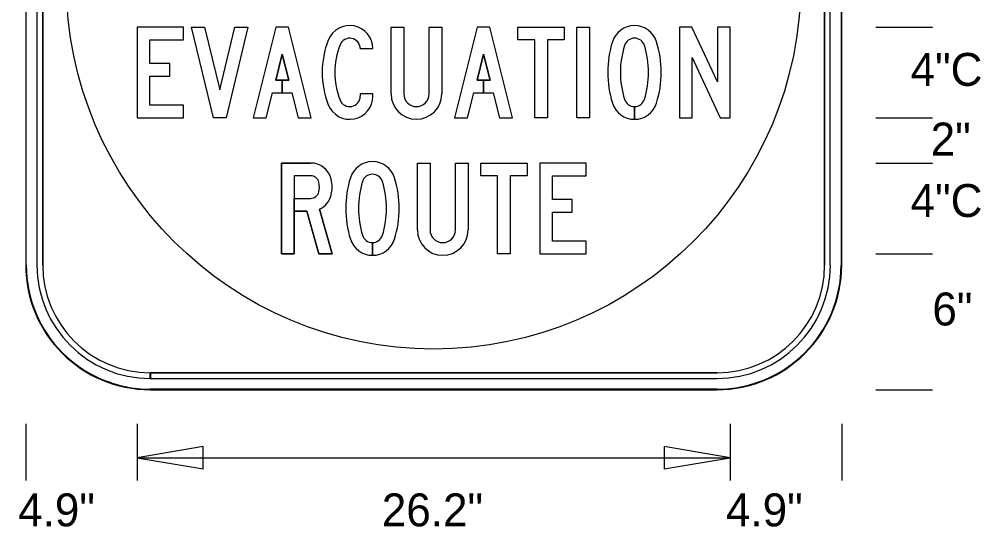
# Model space of a CAD drawing. Extents: x 0 to 770, y 0 to 495.
# Drawn here: x 644.3 to 746.6, y 366.6 to 420.6 of the extents above; entities that cross this region are included whole.
import ezdxf

# ---------------------------------------------------------------- set-up
doc = ezdxf.new("R2010")
doc.units = 0
for name, color, linetype in [('Dimension', 7, 'Continuous'), ('GSBWFill', 7, 'Continuous'), ('GSColorFill', 7, 'Continuous'), ('GSDims', 7, 'Continuous'), ('GSOutline', 7, 'Continuous'), ('IndexDetail_0', 7, 'Continuous'), ('TextStructures', 7, 'Continuous')]:
    doc.layers.add(name, color=color, linetype=linetype)

msp = doc.modelspace()

# ---------------------------------------------------------------- linework, layer by layer
at = {"layer": 'Dimension'}
for points in [[(656.84, 373.93), (663.86, 372.75), (663.86, 375.12)], [(719.93, 373.93), (712.91, 375.12), (712.91, 372.75)]]:
    msp.add_lwpolyline(points, close=True, dxfattribs=at)
at = {"layer": 'GSBWFill'}
for p, q in [((644.98, 454.72), (644.98, 394.43)), ((646.18, 454.72), (646.18, 394.43)), ((646.79, 394.43), (646.79, 454.72)), ((729.98, 454.72), (729.98, 394.43)), ((730.58, 394.43), (730.58, 454.72)), ((731.79, 394.43), (731.79, 454.72)), ((685.2, 419.75), (685.2, 412.64)), ((680.57, 417.46), (681.92, 417.46)), ((709.75, 411.29), (709.75, 409.94)), ((709.75, 409.94), (709.75, 411.29)), ((688, 405.28), (688, 398.17)), ((675.28, 401.52), (675.28, 401.52)), ((681.87, 396.82), (681.87, 395.47)), ((681.87, 395.47), (681.87, 396.82)), ((658.24, 382.37), (658.24, 382.98)), ((718.53, 382.98), (658.25, 382.98)), ((658.25, 382.98), (658.25, 382.37)), ((658.25, 382.37), (718.53, 382.37)), ((658.24, 381.17), (718.53, 381.17))]:
    msp.add_line(p, q, dxfattribs=at)
for points in [[(658.19, 411.46), (658.19, 414.54), (660.31, 414.54), (660.31, 415.89), (658.19, 415.89), (658.19, 418.4), (661.76, 418.4), (661.76, 419.75), (656.84, 419.75), (656.84, 410.11), (661.76, 410.11), (661.76, 411.46)], [(662.63, 419.75), (664.02, 419.75), (665.62, 413.08), (667.22, 419.75), (668.61, 419.75), (666.3, 410.11), (664.95, 410.11)], [(672.28, 414.11), (671.58, 414.11), (672.28, 416.88), (672.97, 414.11), (672.28, 414.11), (672.28, 412.76), (673.31, 412.76), (673.97, 410.11), (675.36, 410.11), (672.95, 419.75), (671.6, 419.75), (669.19, 410.11), (670.58, 410.11), (671.24, 412.76), (672.28, 412.76)], [(693.69, 414.11), (693, 414.11), (693.69, 416.88), (694.38, 414.11), (693.69, 414.11), (693.69, 412.76), (694.72, 412.76), (695.38, 410.11), (696.78, 410.11), (694.36, 419.75), (693.01, 419.75), (690.6, 410.11), (691.99, 410.11), (692.66, 412.76), (693.69, 412.76)], [(699.14, 418.4), (697.35, 418.4), (697.35, 419.75), (702.27, 419.75), (702.27, 418.4), (700.49, 418.4), (700.49, 410.11), (699.14, 410.11)], [(703.62, 419.75), (704.97, 419.75), (704.97, 410.11), (703.62, 410.11)], [(718.86, 410.11), (719.93, 410.11), (719.93, 419.75), (718.58, 419.75), (718.58, 413.92), (715.86, 419.75), (714.52, 419.75), (714.52, 410.11), (715.87, 410.11), (715.87, 416.52)], [(695.18, 403.93), (693.4, 403.93), (693.4, 405.28), (698.32, 405.28), (698.32, 403.93), (696.53, 403.93), (696.53, 395.64), (695.18, 395.64)], [(701.02, 396.99), (701.02, 400.07), (703.13, 400.07), (703.13, 401.42), (701.02, 401.42), (701.02, 403.93), (704.59, 403.93), (704.59, 405.28), (699.67, 405.28), (699.67, 395.64), (704.59, 395.64), (704.59, 396.99)]]:
    msp.add_lwpolyline(points, close=True, dxfattribs=at)
for points in [[(683.85, 412.64), (683.85, 419.75), (685.2, 419.75)], [(687.9, 412.64), (687.9, 419.75), (689.25, 419.75), (689.25, 412.64)], [(681.92, 412.4), (681.92, 412.66), (680.57, 412.66), (680.57, 412.4)], [(675.28, 403.93), (673.53, 403.93), (673.53, 395.64), (672.18, 395.64), (672.18, 405.28), (675.28, 405.28)], [(686.65, 398.17), (686.65, 405.28), (688, 405.28)], [(690.7, 398.17), (690.7, 405.28), (692.05, 405.28), (692.05, 398.17)], [(676.23, 400.38), (677.58, 395.64), (676.18, 395.64), (674.89, 400.17), (673.53, 400.17), (673.53, 401.52), (675.28, 401.52)]]:
    msp.add_lwpolyline(points, dxfattribs=at)
for centre, radius, start, end in [((709.75, 417.46), 2.46, 17.3283, 162.6717), ((709.75, 417.46), 1.11, 17.3283, 162.6717), ((717.86, 414.93), 10.96, 162.6717, 197.3283), ((717.86, 414.93), 9.61, 162.6717, 197.3283), ((701.63, 414.93), 9.61, 342.6717, 17.3283), ((701.63, 414.93), 10.96, 342.6717, 17.3283), ((686.55, 412.64), 2.7, 180, 0), ((686.55, 412.64), 1.35, 180, 0), ((709.75, 412.4), 2.46, 197.3283, 270), ((709.75, 412.4), 1.11, 197.3283, 270), ((709.75, 412.4), 1.11, 270.0249, 342.6717), ((709.75, 412.4), 2.46, 270.0112, 342.6717), ((675.28, 403.02), 2.27, 13.8865, 90), ((681.87, 402.99), 2.46, 17.3283, 162.6717), ((681.87, 402.99), 1.11, 17.3283, 162.6717), ((675.28, 403.02), 0.916, 13.8865, 90), ((674.11, 402.73), 2.12, 346.1135, 13.8865), ((674.11, 402.73), 3.47, 346.1135, 13.8865), ((689.99, 400.46), 10.96, 162.6717, 197.3283), ((689.99, 400.46), 9.61, 162.6717, 197.3283), ((673.76, 400.46), 9.61, 342.6717, 17.3283), ((673.76, 400.46), 10.96, 342.6717, 17.3283), ((675.28, 402.44), 0.916, 270, 346.1135), ((675.28, 402.44), 2.27, 294.8221, 346.1135), ((689.35, 398.17), 2.7, 180, 0), ((689.35, 398.17), 1.35, 180, 0), ((681.87, 397.93), 2.46, 197.3283, 270), ((681.87, 397.93), 1.11, 197.3283, 270), ((681.87, 397.93), 1.11, 270.0249, 342.6717), ((681.87, 397.93), 2.46, 270.0112, 342.6717), ((658.24, 394.43), 13.26, 180, 270), ((658.24, 394.43), 12.06, 180, 270), ((658.24, 394.43), 11.45, 180, 270), ((718.53, 394.43), 12.06, 270, 0), ((718.53, 394.43), 11.45, 270, 0), ((718.53, 394.43), 13.26, 270, 0)]:
    msp.add_arc(centre, radius, start, end, dxfattribs=at)
for centre, major_axis, start_param, end_param in [((679.46, 417.46), (0, 2.46), 4.712389, 7.477539), ((679.46, 417.46), (0, 1.11), 4.712389, 7.477539), ((685.87, 414.93), (0, 9.35), 1.194353, 1.947239), ((685.87, 414.93), (0, 8), 1.194353, 1.947239), ((679.46, 412.4), (0, 2.46), 1.947239, 4.712389), ((679.46, 412.4), (0, 1.11), 1.947239, 4.712389)]:
    msp.add_ellipse(centre, major_axis=major_axis, ratio=0.999991, start_param=start_param, end_param=end_param, dxfattribs=at)
at = {"layer": 'GSColorFill'}
for p, q in [((644.98, 454.72), (644.98, 394.43)), ((644.98, 454.72), (644.98, 394.43)), ((645.04, 394.43), (645.04, 454.72)), ((646.18, 454.72), (646.18, 394.43)), ((646.79, 394.43), (646.79, 454.72)), ((729.98, 454.72), (729.98, 394.43)), ((730.58, 394.43), (730.58, 454.72)), ((731.73, 454.72), (731.73, 394.43)), ((731.79, 394.43), (731.79, 454.72)), ((731.79, 394.43), (731.79, 454.72)), ((685.2, 419.75), (685.2, 412.64)), ((680.57, 417.46), (681.92, 417.46)), ((709.75, 411.29), (709.75, 409.94)), ((709.75, 409.94), (709.75, 411.29)), ((688, 405.28), (688, 398.17)), ((675.28, 401.52), (675.28, 401.52)), ((681.87, 396.82), (681.87, 395.47)), ((681.87, 395.47), (681.87, 396.82)), ((658.24, 382.37), (658.24, 382.98)), ((718.53, 382.98), (658.25, 382.98)), ((658.25, 382.98), (658.25, 382.37)), ((658.25, 382.37), (718.53, 382.37)), ((658.24, 381.17), (658.24, 381.23)), ((718.53, 381.23), (658.24, 381.23)), ((658.24, 381.23), (658.24, 381.17)), ((658.24, 381.17), (718.53, 381.17)), ((658.24, 381.17), (718.53, 381.17))]:
    msp.add_line(p, q, dxfattribs=at)
for points in [[(658.19, 411.46), (658.19, 414.54), (660.31, 414.54), (660.31, 415.89), (658.19, 415.89), (658.19, 418.4), (661.76, 418.4), (661.76, 419.75), (656.84, 419.75), (656.84, 410.11), (661.76, 410.11), (661.76, 411.46)], [(662.63, 419.75), (664.02, 419.75), (665.62, 413.08), (667.22, 419.75), (668.61, 419.75), (666.3, 410.11), (664.95, 410.11)], [(672.28, 414.11), (671.58, 414.11), (672.28, 416.88), (672.97, 414.11), (672.28, 414.11), (672.28, 412.76), (673.31, 412.76), (673.97, 410.11), (675.36, 410.11), (672.95, 419.75), (671.6, 419.75), (669.19, 410.11), (670.58, 410.11), (671.24, 412.76), (672.28, 412.76)], [(693.69, 414.11), (693, 414.11), (693.69, 416.88), (694.38, 414.11), (693.69, 414.11), (693.69, 412.76), (694.72, 412.76), (695.38, 410.11), (696.78, 410.11), (694.36, 419.75), (693.01, 419.75), (690.6, 410.11), (691.99, 410.11), (692.66, 412.76), (693.69, 412.76)], [(699.14, 418.4), (697.35, 418.4), (697.35, 419.75), (702.27, 419.75), (702.27, 418.4), (700.49, 418.4), (700.49, 410.11), (699.14, 410.11)], [(703.62, 419.75), (704.97, 419.75), (704.97, 410.11), (703.62, 410.11)], [(718.86, 410.11), (719.93, 410.11), (719.93, 419.75), (718.58, 419.75), (718.58, 413.92), (715.86, 419.75), (714.52, 419.75), (714.52, 410.11), (715.87, 410.11), (715.87, 416.52)], [(695.18, 403.93), (693.4, 403.93), (693.4, 405.28), (698.32, 405.28), (698.32, 403.93), (696.53, 403.93), (696.53, 395.64), (695.18, 395.64)], [(701.02, 396.99), (701.02, 400.07), (703.13, 400.07), (703.13, 401.42), (701.02, 401.42), (701.02, 403.93), (704.59, 403.93), (704.59, 405.28), (699.67, 405.28), (699.67, 395.64), (704.59, 395.64), (704.59, 396.99)]]:
    msp.add_lwpolyline(points, close=True, dxfattribs=at)
for points in [[(683.85, 412.64), (683.85, 419.75), (685.2, 419.75)], [(687.9, 412.64), (687.9, 419.75), (689.25, 419.75), (689.25, 412.64)], [(681.92, 412.4), (681.92, 412.66), (680.57, 412.66), (680.57, 412.4)], [(675.28, 403.93), (673.53, 403.93), (673.53, 395.64), (672.18, 395.64), (672.18, 405.28), (675.28, 405.28)], [(686.65, 398.17), (686.65, 405.28), (688, 405.28)], [(690.7, 398.17), (690.7, 405.28), (692.05, 405.28), (692.05, 398.17)], [(676.23, 400.38), (677.58, 395.64), (676.18, 395.64), (674.89, 400.17), (673.53, 400.17), (673.53, 401.52), (675.28, 401.52)]]:
    msp.add_lwpolyline(points, dxfattribs=at)
for centre, radius, start, end in [((709.75, 417.46), 2.46, 17.3283, 162.6717), ((709.75, 417.46), 1.11, 17.3283, 162.6717), ((717.86, 414.93), 10.96, 162.6717, 197.3283), ((717.86, 414.93), 9.61, 162.6717, 197.3283), ((701.63, 414.93), 9.61, 342.6717, 17.3283), ((701.63, 414.93), 10.96, 342.6717, 17.3283), ((686.55, 412.64), 2.7, 180, 0), ((686.55, 412.64), 1.35, 180, 0), ((709.75, 412.4), 2.46, 197.3283, 270), ((709.75, 412.4), 1.11, 197.3283, 270), ((709.75, 412.4), 1.11, 270.0249, 342.6717), ((709.75, 412.4), 2.46, 270.0112, 342.6717), ((675.28, 403.02), 2.27, 13.8865, 90), ((681.87, 402.99), 2.46, 17.3283, 162.6717), ((681.87, 402.99), 1.11, 17.3283, 162.6717), ((675.28, 403.02), 0.916, 13.8865, 90), ((674.11, 402.73), 2.12, 346.1135, 13.8865), ((674.11, 402.73), 3.47, 346.1135, 13.8865), ((689.99, 400.46), 10.96, 162.6717, 197.3283), ((689.99, 400.46), 9.61, 162.6717, 197.3283), ((673.76, 400.46), 9.61, 342.6717, 17.3283), ((673.76, 400.46), 10.96, 342.6717, 17.3283), ((675.28, 402.44), 0.916, 270, 346.1135), ((675.28, 402.44), 2.27, 294.8221, 346.1135), ((689.35, 398.17), 2.7, 180, 0), ((689.35, 398.17), 1.35, 180, 0), ((681.87, 397.93), 2.46, 197.3283, 270), ((681.87, 397.93), 1.11, 197.3283, 270), ((681.87, 397.93), 1.11, 270.0249, 342.6717), ((681.87, 397.93), 2.46, 270.0112, 342.6717), ((658.24, 394.43), 13.26, 180, 270), ((658.24, 394.43), 13.26, 180, 270), ((658.24, 394.43), 13.2, 180, 270), ((658.24, 394.43), 12.06, 180, 270), ((658.24, 394.43), 11.45, 180, 270), ((718.53, 394.43), 13.26, 270, 0), ((718.53, 394.43), 12.06, 270, 0), ((718.53, 394.43), 11.45, 270, 0), ((718.53, 394.43), 13.26, 270, 0), ((718.53, 394.43), 13.2, 270, 0)]:
    msp.add_arc(centre, radius, start, end, dxfattribs=at)
for centre, major_axis, start_param, end_param in [((679.46, 417.46), (0, 2.46), 4.712389, 7.477539), ((679.46, 417.46), (0, 1.11), 4.712389, 7.477539), ((685.87, 414.93), (0, 9.35), 1.194353, 1.947239), ((685.87, 414.93), (0, 8), 1.194353, 1.947239), ((679.46, 412.4), (0, 2.46), 1.947239, 4.712389), ((679.46, 412.4), (0, 1.11), 1.947239, 4.712389)]:
    msp.add_ellipse(centre, major_axis=major_axis, ratio=0.999991, start_param=start_param, end_param=end_param, dxfattribs=at)
at = {"layer": 'GSDims'}
for p, q in [((735.41, 419.75), (741.44, 419.75)), ((735.41, 419.75), (741.44, 419.75)), ((735.41, 410.11), (741.44, 410.11)), ((735.41, 410.11), (741.44, 410.11)), ((735.41, 405.28), (741.44, 405.28)), ((735.41, 405.28), (741.44, 405.28)), ((735.41, 395.64), (741.44, 395.64)), ((735.41, 395.64), (741.44, 395.64)), ((735.41, 381.17), (741.44, 381.17)), ((644.98, 377.55), (644.98, 371.52)), ((656.84, 377.55), (656.84, 371.52)), ((656.84, 377.55), (656.84, 371.52)), ((719.93, 377.55), (719.93, 371.52)), ((719.93, 377.55), (719.93, 371.52)), ((731.79, 377.55), (731.79, 371.52)), ((656.84, 373.93), (719.93, 373.93))]:
    msp.add_line(p, q, dxfattribs=at)
at = {"layer": 'GSOutline'}
for p, q in [((644.98, 454.72), (644.98, 394.43)), ((646.18, 454.72), (646.18, 394.43)), ((646.79, 454.72), (646.79, 394.43)), ((729.98, 394.43), (729.98, 454.72)), ((730.58, 394.43), (730.58, 454.72)), ((731.79, 394.43), (731.79, 454.72)), ((685.2, 419.75), (685.2, 412.64)), ((680.57, 417.46), (681.92, 417.46)), ((675.28, 405.28), (672.18, 405.28)), ((688, 405.28), (688, 398.17)), ((675.28, 403.93), (675.28, 403.93)), ((658.24, 382.98), (718.53, 382.98)), ((658.24, 382.37), (718.53, 382.37)), ((658.24, 381.17), (718.53, 381.17))]:
    msp.add_line(p, q, dxfattribs=at)
for points in [[(658.19, 411.46), (658.19, 414.54), (660.31, 414.54), (660.31, 415.89), (658.19, 415.89), (658.19, 418.4), (661.76, 418.4), (661.76, 419.75), (656.84, 419.75), (656.84, 410.11), (661.76, 410.11), (661.76, 411.46)], [(662.63, 419.75), (664.02, 419.75), (665.62, 413.08), (667.22, 419.75), (668.61, 419.75), (666.3, 410.11), (664.95, 410.11)], [(671.24, 412.76), (673.31, 412.76), (673.97, 410.11), (675.36, 410.11), (672.95, 419.75), (671.6, 419.75), (669.19, 410.11), (670.58, 410.11)], [(692.66, 412.76), (694.72, 412.76), (695.38, 410.11), (696.78, 410.11), (694.36, 419.75), (693.01, 419.75), (690.6, 410.11), (691.99, 410.11)], [(699.14, 418.4), (697.35, 418.4), (697.35, 419.75), (702.27, 419.75), (702.27, 418.4), (700.49, 418.4), (700.49, 410.11), (699.14, 410.11)], [(703.62, 419.75), (704.97, 419.75), (704.97, 410.11), (703.62, 410.11)], [(718.86, 410.11), (719.93, 410.11), (719.93, 419.75), (718.58, 419.75), (718.58, 413.92), (715.86, 419.75), (714.52, 419.75), (714.52, 410.11), (715.87, 410.11), (715.87, 416.52)], [(672.97, 414.11), (672.28, 416.88), (671.58, 414.11)], [(694.38, 414.11), (693.69, 416.88), (693, 414.11)], [(695.18, 403.93), (693.4, 403.93), (693.4, 405.28), (698.32, 405.28), (698.32, 403.93), (696.53, 403.93), (696.53, 395.64), (695.18, 395.64)], [(701.02, 396.99), (701.02, 400.07), (703.13, 400.07), (703.13, 401.42), (701.02, 401.42), (701.02, 403.93), (704.59, 403.93), (704.59, 405.28), (699.67, 405.28), (699.67, 395.64), (704.59, 395.64), (704.59, 396.99)]]:
    msp.add_lwpolyline(points, close=True, dxfattribs=at)
for points in [[(683.85, 412.64), (683.85, 419.75), (685.2, 419.75)], [(687.9, 412.64), (687.9, 419.75), (689.25, 419.75), (689.25, 412.64)], [(681.92, 412.4), (681.92, 412.66), (680.57, 412.66), (680.57, 412.4)], [(672.18, 405.28), (672.18, 395.64), (673.53, 395.64), (673.53, 400.17), (674.89, 400.17), (676.18, 395.64), (677.58, 395.64), (676.23, 400.38)], [(686.65, 398.17), (686.65, 405.28), (688, 405.28)], [(690.7, 398.17), (690.7, 405.28), (692.05, 405.28), (692.05, 398.17)], [(675.28, 403.93), (673.53, 403.93), (673.53, 401.52), (675.28, 401.52)]]:
    msp.add_lwpolyline(points, dxfattribs=at)
for centre, radius, start, end in [((709.75, 417.46), 2.46, 17.3283, 162.6717), ((709.75, 417.46), 1.11, 17.3283, 162.6717), ((717.86, 414.93), 10.96, 162.6717, 197.3283), ((717.86, 414.93), 9.61, 162.6717, 197.3283), ((701.63, 414.93), 9.61, 342.6717, 17.3283), ((701.63, 414.93), 10.96, 342.6717, 17.3283), ((686.55, 412.64), 2.7, 180, 0), ((686.55, 412.64), 1.35, 180, 0), ((709.75, 412.4), 2.46, 197.3283, 342.6717), ((709.75, 412.4), 1.11, 197.3283, 342.6717), ((675.28, 403.02), 2.27, 13.8865, 90), ((681.87, 402.99), 2.46, 17.3283, 162.6717), ((681.87, 402.99), 1.11, 17.3283, 162.6717), ((675.28, 403.02), 0.916, 13.8865, 90), ((674.11, 402.73), 2.12, 346.1135, 13.8865), ((674.11, 402.73), 3.47, 346.1135, 13.8865), ((689.99, 400.46), 10.96, 162.6717, 197.3283), ((689.99, 400.46), 9.61, 162.6717, 197.3283), ((673.76, 400.46), 9.61, 342.6717, 17.3283), ((673.76, 400.46), 10.96, 342.6717, 17.3283), ((675.28, 402.44), 0.916, 270, 346.1135), ((675.28, 402.44), 2.27, 294.8221, 346.1135), ((689.35, 398.17), 2.7, 180, 0), ((689.35, 398.17), 1.35, 180, 0), ((681.87, 397.93), 2.46, 197.3283, 342.6717), ((681.87, 397.93), 1.11, 197.3283, 342.6717), ((658.24, 394.43), 13.26, 180, 270), ((658.24, 394.43), 12.06, 180, 270), ((658.24, 394.43), 11.45, 180, 270), ((718.53, 394.43), 12.06, 270, 0), ((718.53, 394.43), 11.45, 270, 0), ((718.53, 394.43), 13.26, 270, 0)]:
    msp.add_arc(centre, radius, start, end, dxfattribs=at)
for centre, major_axis, start_param, end_param in [((679.46, 417.46), (0, 2.46), 4.712389, 7.477539), ((679.46, 417.46), (0, 1.11), 4.712389, 7.477539), ((685.87, 414.93), (0, 9.35), 1.194353, 1.947239), ((685.87, 414.93), (0, 8), 1.194353, 1.947239), ((679.46, 412.4), (0, 2.46), 1.947239, 4.712389), ((679.46, 412.4), (0, 1.11), 1.947239, 4.712389)]:
    msp.add_ellipse(centre, major_axis=major_axis, ratio=0.999991, start_param=start_param, end_param=end_param, dxfattribs=at)
at = {"layer": 'IndexDetail_0'}
msp.add_circle((688.38, 424.57), 39.07, dxfattribs=at)

# ---------------------------------------------------------------- texts
at = {"layer": 'TextStructures'}
for s, p in [('4"C', (739.12, 413.5)), ('2"', (741.26, 406.09)), ('4"C', (739.12, 399.55)), ('6"', (741.44, 388.01)), ('4.9"', (644.18, 366.64)), ('26.2"', (682.87, 366.64)), ('4.9"', (719.48, 366.64))]:
    msp.add_text(s, height=3.5, dxfattribs=at).set_placement(p)

doc.saveas('drawing.dxf')
